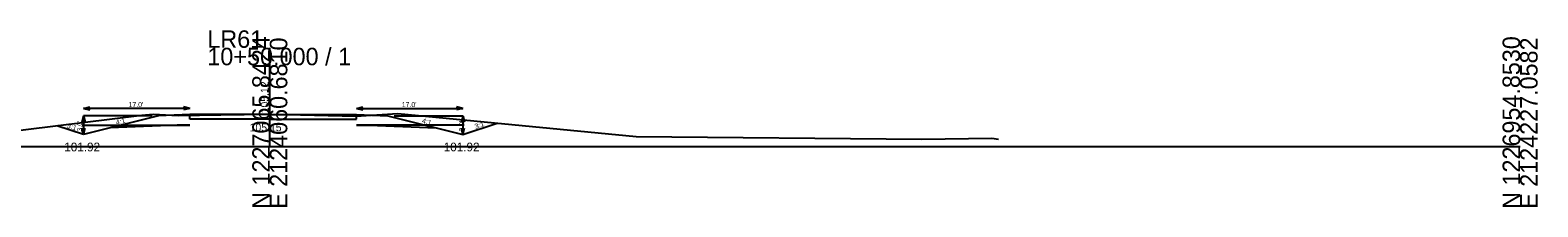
# Model space of a CAD drawing. Extents: x -26 to 1403, y -10 to 9574.
# Drawn here: x 1161.7 to 1402.8, y 490.3 to 518.7 of the extents above; entities that cross this region are included whole.
import ezdxf

# ---------------------------------------------------------------- set-up
doc = ezdxf.new("R2010")
doc.units = 0
for name, color, linetype in [('XS_CELL', 7, 'Continuous'), ('XS_P_FINISHED_GRADE', 7, 'Continuous'), ('XS_P_FINISHED_GRADE_ELEV_TX', 7, 'Continuous'), ('XS_P_SUBGRADE_GRANULAR', 7, 'Continuous'), ('XS_P_SUBGRADE_PAVEMENT', 7, 'Continuous'), ('XS_P_TX_CLEARZONE', 7, 'Continuous'), ('XS_P_TX_DCH', 7, 'Continuous'), ('XS_P_TX_FS_BS', 7, 'Continuous'), ('XS_X_GROUND', 7, 'Continuous'), ('XS_X_GROUND_TX', 7, 'Continuous')]:
    doc.layers.add(name, color=color, linetype=linetype)

msp = doc.modelspace()

# ---------------------------------------------------------------- linework, layer by layer
at = {"layer": 'XS_CELL'}
for p, q in [((1200, 500), (1200, 515.83)), ((1000, 500), (1200, 500)), ((1200, 500), (1400, 500))]:
    msp.add_line(p, q, dxfattribs=at)
at = {"layer": 'XS_P_FINISHED_GRADE'}
for p, q in [((1182.19, 504.92), (1170.19, 501.92)), ((1187.19, 505.12), (1182.19, 504.92)), ((1200, 505.12), (1187.19, 505.12)), ((1200, 505.12), (1213.89, 505.12)), ((1213.89, 505.12), (1218.89, 504.92)), ((1218.89, 504.92), (1230.89, 501.92)), ((1170.19, 501.92), (1165.95, 503.34)), ((1230.89, 501.92), (1236.36, 503.74))]:
    msp.add_line(p, q, dxfattribs=at)
at = {"layer": 'XS_P_SUBGRADE_GRANULAR'}
for p, q in [((1169.99, 503.42), (1187.19, 503.42)), ((1185.19, 503.42), (1174.48, 502.99)), ((1187.19, 503.42), (1185.19, 503.42)), ((1231.09, 503.42), (1213.89, 503.42)), ((1213.89, 503.42), (1215.89, 503.42)), ((1215.89, 503.42), (1226.61, 502.99))]:
    msp.add_line(p, q, dxfattribs=at)
at = {"layer": 'XS_P_SUBGRADE_PAVEMENT'}
for p, q in [((1187.19, 504.37), (1187.19, 505.12)), ((1200, 504.37), (1187.19, 504.37)), ((1200, 504.37), (1213.89, 504.37)), ((1213.89, 504.37), (1213.89, 505.12))]:
    msp.add_line(p, q, dxfattribs=at)
at = {"layer": 'XS_P_TX_CLEARZONE'}
for p, q in [((1170.19, 504.92), (1169.94, 503.92)), ((1170.19, 506.12), (1171.19, 506.37)), ((1170.19, 506.12), (1171.19, 505.87)), ((1187.19, 506.12), (1170.19, 506.12)), ((1170.19, 504.92), (1170.44, 503.92)), ((1170.19, 504.92), (1170.19, 501.92)), ((1181.19, 504.92), (1170.19, 504.92)), ((1187.19, 506.12), (1186.19, 506.37)), ((1187.19, 506.12), (1186.19, 505.87)), ((1213.89, 506.12), (1214.89, 506.37)), ((1213.89, 506.12), (1214.89, 505.87)), ((1213.89, 506.12), (1230.89, 506.12)), ((1219.89, 504.92), (1230.89, 504.92)), ((1230.89, 506.12), (1229.89, 506.37)), ((1230.89, 506.12), (1229.89, 505.87)), ((1230.89, 504.92), (1230.64, 503.92)), ((1230.89, 504.92), (1230.89, 501.92)), ((1230.89, 504.92), (1231.14, 503.92)), ((1170.19, 501.92), (1169.94, 502.92)), ((1170.19, 501.92), (1170.44, 502.92)), ((1230.89, 501.92), (1230.64, 502.92)), ((1230.89, 501.92), (1231.14, 502.92))]:
    msp.add_line(p, q, dxfattribs=at)
at = {"layer": 'XS_X_GROUND'}
for p, q in [((1154.71, 501.96), (1179.53, 505)), ((1179.53, 505), (1181.33, 505.21)), ((1181.33, 505.21), (1185.35, 504.96)), ((1185.35, 504.96), (1192.18, 505.06)), ((1192.18, 505.06), (1199.67, 505.16)), ((1199.67, 505.16), (1200, 505.15)), ((1200, 505.15), (1204.9, 505.06)), ((1204.9, 505.06), (1213.78, 504.88)), ((1213.78, 504.88), (1220.49, 505.28)), ((1220.49, 505.28), (1222.13, 505.12)), ((1222.13, 505.12), (1258.6, 501.59)), ((1258.6, 501.59), (1304.32, 501.17)), ((1304.32, 501.17), (1315.48, 501.33)), ((1315.48, 501.33), (1316.54, 501.2))]:
    msp.add_line(p, q, dxfattribs=at)

# ---------------------------------------------------------------- texts
at = {"layer": 'XS_CELL'}
for s, p in [('LR61', (1190, 515.83)), ('10+50.000 / 1', (1190, 513.03))]:
    msp.add_text(s, height=2.8, dxfattribs=at).set_placement(p)
for s, p in [('N 1227065.8424', (1200, 490)), ('E 2124060.6810', (1202.8, 490)), ('N 1226954.8530', (1400, 490)), ('E 2124227.0582', (1402.8, 490))]:
    msp.add_text(s, height=2.8, rotation=90, dxfattribs=at).set_placement(p)
at = {"layer": 'XS_P_FINISHED_GRADE_ELEV_TX'}
msp.add_text('105.12', height=1.25, rotation=90, dxfattribs=at).set_placement((1199.8, 505.32))
at = {"layer": 'XS_P_TX_CLEARZONE'}
for p in [(1177.41, 506.32), (1221.11, 506.32)]:
    msp.add_text("17.0'", height=0.8, dxfattribs=at).set_placement(p)
for p in [(1169.99, 502.4), (1231.09, 502.4)]:
    msp.add_text("3.0'", height=0.8, rotation=90, dxfattribs=at).set_placement(p)
at = {"layer": 'XS_P_TX_DCH'}
for p in [(1167.12, 499.22), (1227.82, 499.22)]:
    msp.add_text('101.92', height=1.4, dxfattribs=at).set_placement(p)
at = {"layer": 'XS_P_TX_FS_BS'}
for s, rotation, p in [('4:1', 14.0343, (1175.48, 503.45)), ('4:1', 345.9663, (1224.28, 503.78)), ('3:1', 341.5675, (1167.49, 503.03)), ('3:1', 18.4317, (1232.92, 502.81))]:
    msp.add_text(s, height=0.8, rotation=rotation, dxfattribs=at).set_placement(p)
at = {"layer": 'XS_X_GROUND_TX'}
msp.add_text('105.15', height=1.25, rotation=360, dxfattribs=at).set_placement((1196.77, 502.43))

doc.saveas('drawing.dxf')
